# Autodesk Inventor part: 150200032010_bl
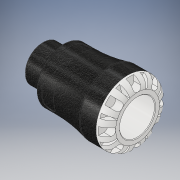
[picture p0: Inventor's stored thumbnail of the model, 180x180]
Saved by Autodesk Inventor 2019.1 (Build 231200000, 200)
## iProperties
Created: 2016-12
Part Number: 150200032010_bl
Material: PVC-Piping
Description: PLASSON G-PLASS Male Adaptor 32X1''
Document SubType Name: Modeling
Designer: KIM
Mass: 61.7504 g
Surface Area: 140.097 cm^2
Volume: 44.1074 cm^3
Density: 1.4 g/cm^3
Appearance: Black Cast
Author: KIM
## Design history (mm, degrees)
derived "150200.ipt"
feature "Solid1::150200.ipt" dims "ScaleForDerivedMember" = 10
tag "TaggingFeature1"
body "Solid1"
other parameters: "d0" = 87 [user parameter], "d1" = 23.94 [user parameter], "d2" = 32 [user parameter], "d4" = 58 [user parameter], "d6" = 57 [user parameter], "d8" = 49.3 [user parameter], "d13" = 7.2 [user parameter], "d14" = 7.2 [user parameter], "d15" = 0 [user parameter], "d17" = 360 deg [user parameter], "d19" = 8 deg [user parameter], "d20" = 0.64 [user parameter], "d21" = 0.64 [user parameter], "d22" = 8 deg [user parameter], "d24" = 0 [user parameter], "d26" = 360 deg [user parameter], "d32" = 0.925 [user parameter], "d33" = 5.8 [user parameter], "d34" = 33.249 [user parameter], "d35" = 2.66667 [user parameter], "d38" = 19 [user parameter], "d39" = 0.99747 [user parameter], "d42" = 11.2 [user parameter], "d43" = 7.36 [user parameter], "d45" = 14.112 [user parameter], "d46" = 0 [user parameter], "d59" = 360 deg [user parameter], "d61" = 9.52 [user parameter], "d62" = 0.64 [user parameter], "d64" = 0 [user parameter], "d65" = 0.58 [user parameter], "d_" = 32 [user parameter], "E_" = 58 [user parameter], "H_" = 87 [user parameter], "l_" = 57 [user parameter], "R_" = 33.249 [user parameter], "l_2" = 19 [user parameter], "d9" = 9 [user parameter], "d11" = 58 [user parameter]
